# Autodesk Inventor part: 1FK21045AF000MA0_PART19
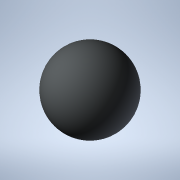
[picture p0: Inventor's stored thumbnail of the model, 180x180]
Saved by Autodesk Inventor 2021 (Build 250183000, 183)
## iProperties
Created: 2025-04
Part Number: 1FK21045AF000MA0_PART19
Material: Generic
Catalog Web Link: www.3dfindit.com
Description: -Servo synchronous motor
Document SubType Name: Modeling
Designer: psAdmin
Mass: 0.137258 g
Surface Area: 1.2868 cm^2
Volume: 0.137258 cm^3
Density: 1 g/cm^3
Appearance: PSOLRGB-212-217-219
Category: PARTsolutions
Title: 1FK21045AF000MA0_PART19
Author: Cadenas PARTsolutions
Comments: Servo synchronous motor
Sending System: PARTsolutions
Preprocessor: ST-DEVELOPER v19.3
PSOL_IDENT_0: {$CADENAS_DATA/23d-libs/siemens_ag/_cat_/8b/0a/1fk21045af000ma0.prj},216 {VTYP=3D},{NB=1FK21045AF000
PSOL_IDENT_1: MA0_PART19},{LINA=1FK21045AF000MA0_PART19},{NN=1FK21045AF000MA0_PART19},{NOPRJ=TRUE},{DATE=19.08.202
PSOL_IDENT_2: 5 14:00:48},{GEOMDATE=30.07.2025 02:00:28},{VERSION=},{LINEID=10},{WBVAR=},{WBNUMERIC=}  {NB=1FK2104
PSOL_IDENT_3: 5AF000MA0_PART19},{LINA=1FK21045AF000MA0_PART19},{KT=DUMMY},{PREVIEW=../../../_pool_/a9/69/p_d211_xx
PSOL_IDENT_4: _00818j.png},{DESCSHORT=SIMOTICS S-1FK2 HD, SINAMICS S210 3AC 400V-480V, 2.4 Nm, 3000 rpm},{DESCLONG=
PSOL_IDENT_5: SIMOTICS S-1FK2 HD servo motor M0=2.4 Nm; PN = 0.75 kW at nN=3000 rpm (380-480 V); PN = 0.375 kW at
PSOL_IDENT_6: nN=1500 rpm (200-240 V); degree of protection IP64; cylindrical shaft D19x40mm; absolute encoder 22-
PSOL_IDENT_7: bit + 12-bit multiturn (encoder AM22DQC); with OCC interface; plug size M17, rotatable; SIMOTICS S-1
PSOL_IDENT_8: FK2 servomotorfor a wide range of uses in industrial environments. SIMOTICS S‑1FK2 servomotors are c
PSOL_IDENT_9: ompact synchronous motors with a high dynamic performance that set themselves apart as a result of t
PSOL_IDENT_10: heir high power density, degree of protection and overload capability. The motors are available in t
PSOL_IDENT_11: wo variants: as High Dynamic variant (highest dynamic performance as a result of the low intrinsic m
PSOL_IDENT_12: oment of inertia for applications demanding a high dynamic performance with low moved masses) - and
PSOL_IDENT_13: as Compact variant (precise and stable closed-loop control for medium up to large moved masses as a
PSOL_IDENT_14: result of a medium intrinsic moment of inertia). SIMOTICSS‑1FK2 servomotors fully exploit their stre
PSOL_IDENT_15: ngths in a system with the SINAMICSS210 frequency converter and simple connection using the one cabl
PSOL_IDENT_16: e connection (OCC). Advantages include the short control and positioning times, fast and precise cor
PSOL_IDENT_17: rection of disturbing quantities as well as stable control with a high dynamic performance. The serv
PSOL_IDENT_18: o motors can be configured to address a wide range of requirements. For example with and without hol
PSOL_IDENT_19: ding brake, IP64 or IP65 degree of protection, singleturn or multiturn absolute encoders - to name j
PSOL_IDENT_20: ust a few. Further, the servomotors are available in different shaft heights extending from 20 to 10
PSOL_IDENT_21: 0. A shaft sealing ring is available to achieve an IP65 degree of protection and for subsequent moun
PSOL_IDENT_22: ting at the motor or as spare part. SIMOTICS - the optimum motor for each and every motion control a
PSOL_IDENT_23: pplication.},{INTNO=195125050112},{SUPPLIERALTNO=1FK2104-5AF00-0MA0},{MANUID=1FK21045AF000MA0},{MANU
PSOL_IDENT_24: NAME=Siemens},{MANUTYPEDESC=Synchronous motor 1FK2-HD 2.4 NM},{AAU732=SIMOTICS},{AAO057=S-1FK2},{AAU
PSOL_IDENT_25: 734=SIMOTICS S-1FK2 HD servo motor M0=2.4 Nm; PN = 0.75 kW at nN=3000 rpm (380-480 V); PN = 0.375 kW
PSOL_IDENT_26: at nN=1500 rpm (200-240 V); degree of protection IP64; cylindrical shaft D19x40mm; absolute encoder
PSOL_IDENT_27: 22-bit + 12-bit multiturn (encoder AM22DQC); with OCC interface; plug size M17, rotatable;},{AAW338=
PSOL_IDENT_28: Synchronous motor 1FK2-HD 2.4 NM},{AAO742=SIMOTICS},{AAO663=4042948692912},{NOCUPEROU=1},{PRICEQUANT
PSOL_IDENT_29: ITY=1},{QUANTITYMIN=1},{QUANTITYINT=1},{CTN=85015100},{COO=DE},{AAO676=1FK2104-5AF00-0MA0},{AAO677=S
PSOL_IDENT_30: iemens AG},{ORDERUNIT=C62},{CONTENTUNIT=C62}
NB: 1FK21045AF000MA0_PART19
NT: Servo synchronous motor
NBSYN: $MANUID._PART19
LINA: 1FK21045AF000MA0_PART19
CATALOG: SIEMENS
PREVIEW: ../../../_pool_/a9/69/p_d211_xx_00818j.png
DESCSHORT: SIMOTICS S-1FK2 HD, SINAMICS S210 3AC 400V-480V, 2.4 Nm, 3000 rpm
DESCLONG: SIMOTICS S-1FK2 HD servo motor M0=2.4 Nm; PN = 0.75 kW at nN=3000 rpm (380-480 V); PN = 0.375 kW at nN=1500 rpm (200-240 V); degree of protection IP64; cylindri
INTNO: 195125050112
SUPPLIERALTNO: 1FK2104-5AF00-0MA0
MANUID: 1FK21045AF000MA0
MANUNAME: Siemens
MANUTYPEDESC: Synchronous motor 1FK2-HD 2.4 NM
AAU732: SIMOTICS
AAO057: S-1FK2
AAU734: SIMOTICS S-1FK2 HD servo motor M0=2.4 Nm; PN = 0.75 kW at nN=3000 rpm (380-480 V); PN = 0.375 kW at nN=1500 rpm (200-240 V); degree of protection IP64; cylindri
AAW338: Synchronous motor 1FK2-HD 2.4 NM
AAO742: SIMOTICS
AAO663: 4042948692912.0
NOCUPEROU: 1
PRICEQUANTITY: 1
QUANTITYMIN: 1
QUANTITYINT: 1
CTN: 85015100
COO: DE
ARTICLENO: 1FK21045AF000MA0_PART19
BOMINFO: 1FK21045AF000MA0_PART19
CREATOR: CADENAS GmbH
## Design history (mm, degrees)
feature "2025_04_17_15_40_42_0766"
body "Solid1"
